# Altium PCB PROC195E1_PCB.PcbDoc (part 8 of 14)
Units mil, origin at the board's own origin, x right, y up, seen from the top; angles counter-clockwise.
Board outline 3110.24 x 2500 mil, 10 copper layers (Top Layer, L02_GND1, L03_SIG1, L04_GND2, L05_PWR1, L06_PWR2, L07_GND3, L08_SIG2, L09_GND4, Bottom Layer), stack 66.407 mil thick; 571 components, 538 nets, 6726 pads, 1286 vias.
Unrouted connection lines stored in the file: 4.
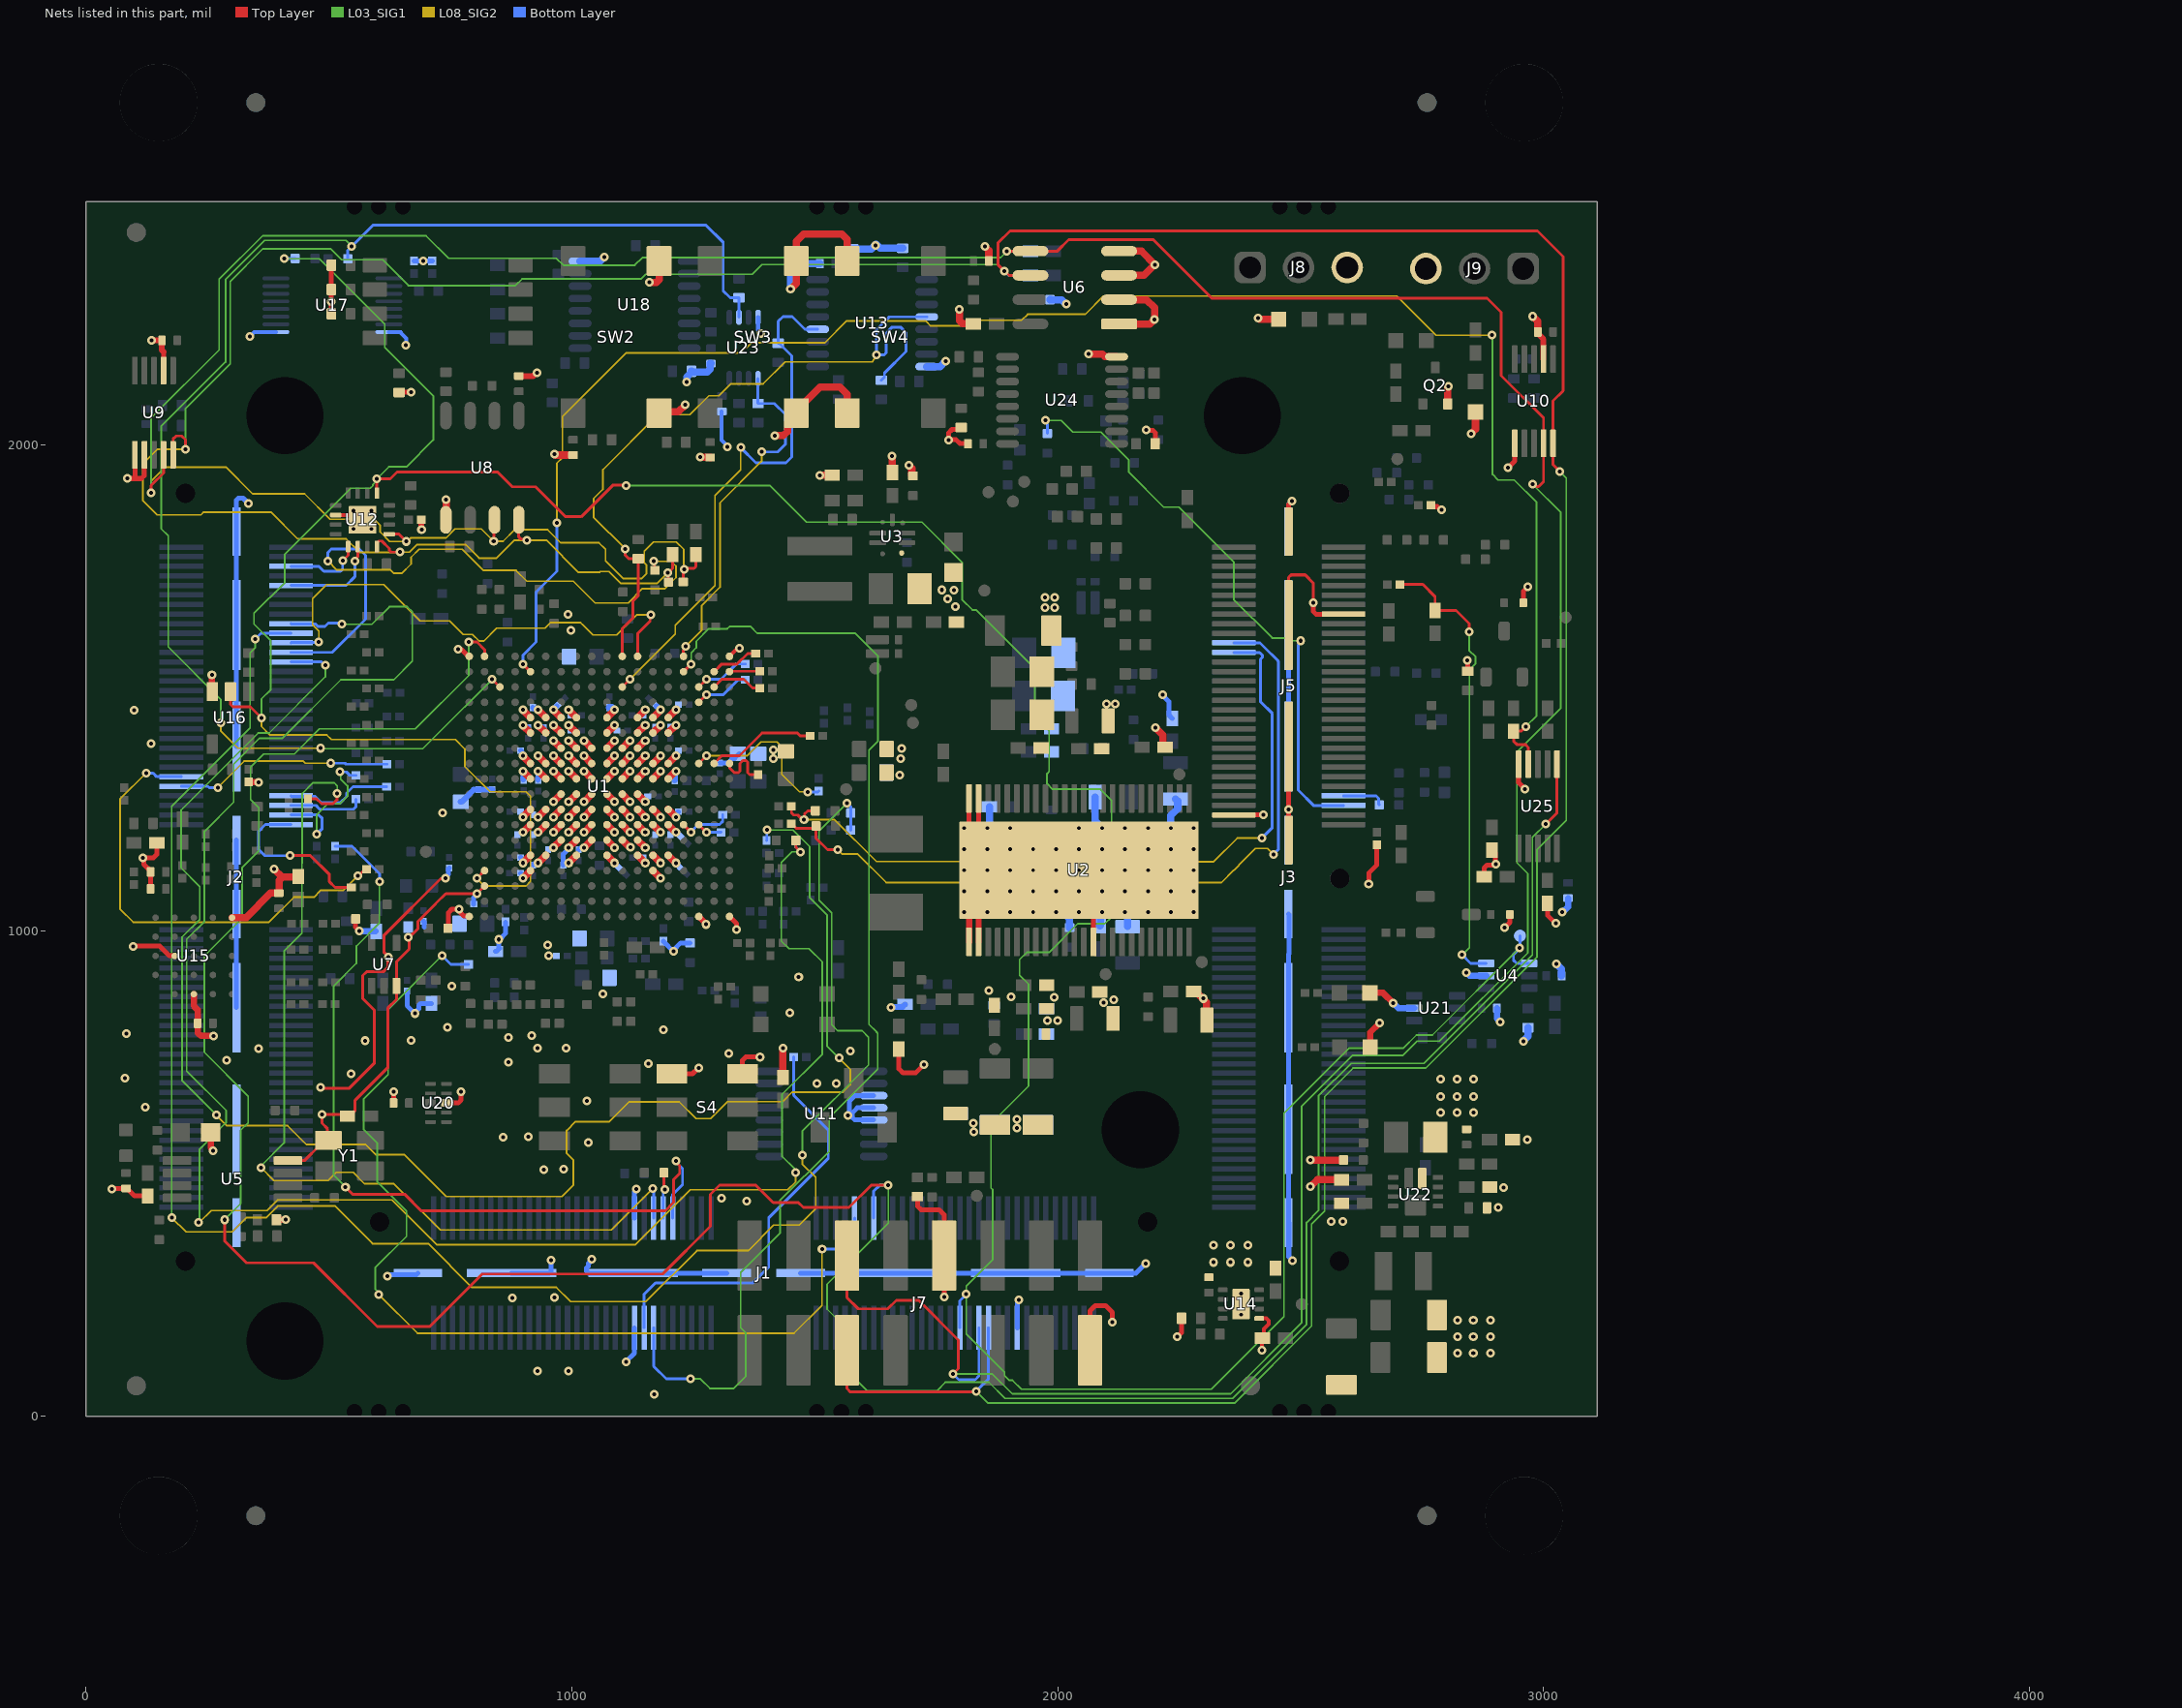
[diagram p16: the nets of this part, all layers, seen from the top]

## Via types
v1: diameter 18, hole 8, Top Layer to Bottom Layer, tented both sides, 1226 vias
v2: diameter 19.68, hole 7.87, Top Layer to Bottom Layer, tented top, 54 vias
v3: diameter 19.68, hole 7.87, Top Layer to Bottom Layer, 4 vias
v4: diameter 19.68, hole 7.87, Top Layer to Bottom Layer, tented both sides, 2 vias

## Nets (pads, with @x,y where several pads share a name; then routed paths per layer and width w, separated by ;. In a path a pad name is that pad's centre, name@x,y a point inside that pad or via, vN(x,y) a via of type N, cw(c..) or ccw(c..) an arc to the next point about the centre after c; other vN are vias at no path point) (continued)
GND: C1.2 C2.2 C3.2 C4.2 C5.2 C6.2 C7.2 C8.2 C9.2 C10.2 C11.2 C12.2 C13.2 C14.2 C15.2 C16.2 C17.2 C18.2 C19.2 C20.2 C21.2 C22.2 C23.2 C24.2 C25.2 C26.2 C27.2 C28.2 C29.2 C30.2 C31.2 C32.2 C33.2 C34.2 C35.2 C36.2 C37.2 C38.2 C39.2 C40.2 C41.2 C42.2 C43.2 C44.2 C45.2 C46.2 C47.2 C48.2 C49.2 C50.2 C51.2 C52.2 C53.2 C54.2 C55.2 C56.2 C57.2 C58.2 C59.1 C60.1 C62.2 C63.2 C64.2 C65.1 C66.1 C67.2 C68.2 C69.2 C70.2 C73.2 C74.2 C75.1 C76.2 C77.2 C78.2 C79.2 C80.2 C81.2 C82.1 C83.1 C84.2 C85.2 C86.2 C87.1 C88.1 C89.1 C90.1 C91.2 C92.2 C93.2 C94.2 C95.2 C96.1 C97.2 C98.2 C99.2 C100.1 C101.2 C102.1 C103.1 C104.2 C105.2 C107.2 C109.2 C111.2 C112.2 C113.2 C114.2 C115.2 C116.2 C117.2 C118.2 C119.2 C122.1 C129.2 C130.1 C131.2 C132.2 C137.2 C138.2 C139.2 C140.2 C141.2 C152.2 C153.1 C154.1 C155.2 C156.2 C157.2 C158.2 C159.2 C160.2 C161.2 C167.2 C168.2 C169.2 C174.2 D5.1 D6.1 D7.1 D8.1 D9.1 D10.1 J1.17 J1.77 J1.78 J1.121 J1.122 J1.123 J1.124 J1.125 J1.126 J1.127 J1.128 J2.121 J2.122 J2.123 J2.124 J2.125 J2.126 J2.127 J2.128 J3.121 J3.122 J3.123 J3.124 J3.125 J3.126 J3.127 J3.128 J5.16 J5.57 J5.P1 J5.P2 J5.P3 J5.P4 J7.2 J7.7 J8.3 J9.3 Q2.2 R2.1 R13.1 R17.1 R26.1 R28.2 R31.1 R32.1 R33.1 R35.1 R42.1 R51.1 R53.1 R69.2 R78.1 R148.2 R166.1 R188.1 R194.1 R200.1 R201.1 R209.1 R227.1 R228.1 R229.1 R230.1 R251.2 R258.2 R259.2 R269.2 R270.2 R271.1 R281.1 R302.2 R303.2 R309.2 SW2.1 SW2.3 SW3.1 SW3.3 SW4.1 SW4.3 U1.A1 U1.A18 U1.E5 U1.E6 U1.E7 U1.E8 U1.E10 U1.E12 U1.E13 U1.E14 U1.F5 U1.F6 U1.F7 U1.F8 U1.F10 U1.F12 U1.F13 U1.F14 U1.G7 U1.G8 U1.G9 U1.G10 U1.G11 U1.G12 U1.H5 U1.H6 U1.H7 U1.H8 U1.H9 U1.H10 U1.H11 U1.H12 U1.H13 U1.H14 U1.J5 U1.J6 U1.J7 U1.J8 U1.J9 U1.J10 U1.J11 U1.J12 U1.J13 U1.J14 U1.K7 U1.K8 U1.K9 U1.K10 U1.K11 U1.K12 U1.L5 U1.L6 U1.L7 U1.L8 U1.L9 U1.L10 U1.L11 U1.L12 U1.L13 U1.L14 U1.M5 U1.M6 U1.M7 U1.M8 U1.M9 U1.M10 U1.M11 U1.M12 U1.M13 U1.M14 U1.N7 U1.N8 U1.N9 U1.N10 U1.N11 U1.N12 U1.P5 U1.P6 U1.P8 U1.P10 U1.P12 U1.P13 U1.P14 U1.R5 U1.R13 U1.T2 U1.V1 U1.V16 U1.V18 U2.1 U2.2 U2.14 U2.47 U2.48 U2.49 U3.4 U4.2 U5.4 U6.1 U6.2 U6.3 U6.4 U7.3 U8.5 U9.1 U9.2 U9.7 U10.1 U10.7 U11.11 U11.12 U11.13 U12.6 U12.17@569.55,1845.49 U13.8 U14.5 U14.9 U15.B3 U15.C1 U15.E5 U16.3 U17.8 U17.9 U18.8 U20.3@742.01,645.23 U21.2 U22.5 U23.4 U24.8 U25.5 Y1.2 | length 14704.5
  Top Layer w5.6: U1.T2@820.66,1091.48 U1.T2@820.66,1091.97
  Top Layer w5.66: 782.6,1076.22 787.91,1076.22 787.96,1076.26 804.87,1076.26 v1(804.91,1076.22)
  Top Layer w5.8: 720.46,1055.73 740.94,1076.22 782.6,1076.22
  Top Layer w6: U5.4@416.14,526.56 449.87,526.56 481.25,557.95 491.46,568.15 Y1.2@499.33,568.15 497.6,569.88 497.6,591.91 486,603.51 v1(486,621.89) 534.81,621.89 C130.1@538.62,618.07 ; v1(482.81,676.91) 483.88,675.84 542.51,675.84 594.13,727.46 594.13,835.85 569.88,860.1 569.88,907.34 577.76,915.23 612.26,915.23 622.08,925.05 v1@622.08,947.14 ; C130.1@538.7,618.15 542.64,618.15 554.45,629.96 554.45,650.72 621.28,717.56 621.28,840.1 639.57,858.39 U7.3@639.57,886.14 639.57,935.97 665.71,962.11 665.71,983.81 v1(663.47,986.04) ; v1(622.52,945.86) 622.52,946.7 613.48,955.74 613.48,989.9 730.55,1106.97 738.82,1106.97 v1(739.87,1108.02) ; v1@666.22,986.5 683.92,1004.2 683.92,1019.19 720.46,1055.73 ; v1(804.91,1076.22) U1.T2@820.66,1091.97 ; J5.P2@2475.38,1628.72 2475.38,1726.89 2480.63,1732.14 2509.46,1732.14 2525.71,1715.88 v1@2525.71,1675.24
  Top Layer w8: U12.6@514.43,1855.34 543.9,1855.34 550.85,1862.28 v3(550.85,1864.2) ; U1.A18@1324.6,1564.41 1339.13,1578.94 1343.12,1578.94 v1(1345.49,1581.3) ; U14.5@2415.32,202.21 2415.82,201.71 2429.4,201.71 2434.39,196.73 2434.39,190.1 2424.82,180.53 2424.82,164.63 C83.1@2421.59,161.4 ; v1(2420.77,136.59) 2420.77,160.68 C83.1@2421.54,161.45
  Top Layer w10: v1(54.07,468.19) 54.71,468.83 82.16,468.83 C116.2@82.8,469.48 84.77,469.48 100.52,453.73 C115.2@127.8,453.73 ; v1(85.51,1931.17) 86.25,1930.43 101.22,1930.43 ; v1(97.8,967.23) 98.56,967.99 152.49,967.99 172.39,948.09 182.85,948.09 U15.B3@182.96,947.98 ; U9.1@101.14,1979.36 101.22,1979.28 101.22,1930.43 ; U9.2@120.82,1979.36 120.03,1978.57 120.03,1936.28 114.17,1930.43 101.22,1930.43 ; C140.2@133.27,1085.78 C137.2@133.27,1120.78 133.27,1122.75 119.26,1136.76 119.26,1148.24 v1(117.72,1149.77) 139.18,1149.77 146.37,1156.96 R200.1@146.37,1180.75 ; U9.7@160.19,2152.59 160.19,2191.35 ; R228.1@505.5,2269.54 v1(505.5,2294.54) R229.1@505.5,2319.54 R230.1@505.5,2369.54 ; R53.1@555.32,1024.24 555.32,1006.96 562.51,999.77 v1(562.51,999.17) ; C152.2@633.35,645.23 633.46,645.33 633.46,667.97 v1(633.56,668.07) ; R227.1@644.79,2107.67 645.33,2108.21 669.06,2108.21 v1(669.6,2108.76) ; U20.3@742.01,645.23 766.52,645.23 772.38,651.08 v1(772.38,668.85) ; R166.1@745.38,1004.78 746.7,1006.11 746.7,1037.26 753.36,1043.92 v1(767.91,1043.92) 769.44,1042.39 769.44,1038.25 777.77,1029.92 788.21,1029.92 U1.V1@789.16,1028.97 ; v1(766.13,1579.58) 767.66,1578.05 773.97,1578.05 787.61,1564.41 U1.A1@789.16,1564.41 ; U1.V18@1324.6,1028.97 1339.02,1014.55 1339.02,1002.8 v1(1339.43,1002.39) ; 1673.3,730.28 1673.3,715.7 1682.16,706.84 1707.6,706.84 v1(1724.57,723.81) ; 1673.3,731.28 C70.2@1673.3,756.03 ; R2.1@1711.47,452.57 1711.47,432.73 1718.71,425.5 1756.16,425.5 1766.47,415.19 J7.7@1766.47,331.06 1766.52,331.02 v1(1766.52,245.52) ; v1(1775.23,2010.01) v1@1775.23,2010.26 ; R259.2@1801.56,2035.56 1797.6,2031.59 1782.44,2031.59 1775.23,2024.39 v1@1775.23,2010.26 ; v2(1807.8,1210.92) 1810.36,1210.92 1817.64,1218.2 U2.48@1817.64,1271.95 ; C160.2@1815.39,2002.06 1814.58,2002.86 1798.42,2002.86 1791.03,2010.26 v1@1775.23,2010.26 ; U2.47@1837.32,1271.95 1837.32,1218.2 1844.6,1210.92 v2(1855.04,1210.92) ; J7.2@2066.47,136.18 2066.47,217.19 2077.3,228.03 2098.73,228.03 2112.67,214.09 v1(2112.67,194.48) ; U2.14@2073.54,976.67 2073.54,1030.42 2080.82,1037.7 v2(2091.26,1037.7) ; v1(2182.67,2030.73) 2184.2,2029.2 2196.47,2029.2 2200.66,2025.01 R258.2@2200.66,2002.06 ; v1(2246.45,164.33) 2246.74,164.33 2254.84,172.43 R42.1@2254.84,202.01 ; J5.57@2362.59,1237.97 v1@2422.96,1237.97 ; J5.P4@2475.38,1186.2 2475.19,1186.4 v1(2475.19,1249.34) 2475.19,1272 2475.38,1272.2 J5.P3@2475.38,1378.72 ; J5.P1@2475.38,1821.24 2475.38,1877.45 v1(2482.09,1884.24) v1(2482.09,1884.24) ; v1(2525.79,1675.17) 2525.79,1657.22 2531.65,1651.36 J5.16@2588.18,1651.36 ; v1(2640.09,1095.94) 2640.28,1096.12 2640.28,1118.49 2656.82,1135.03 R31.1@2656.82,1176.2 ; R26.1@2767.94,1875.9 2771.21,1872.63 2781.02,1872.63 2787.79,1865.86 v1(2789.96,1865.86) ; v1(2843.1,1556.55) 2843.46,1556.19 2843.46,1532.33 R281.1@2844.06,1531.73 ; R270.2@2877.76,1110.57 2877.76,1129.22 2883.62,1135.07 2900.4,1135.07 v1(2901.93,1136.61) 2901.93,1138.77 2900.32,1140.38 2900.32,1158.85 R269.2@2893.81,1165.35 ; v1(2919.51,1005.83) 2930.59,1016.91 D9.1@2930.59,1033.04 ; v1(2926.97,1952.88) 2940.74,1966.65 U10.1@2940.74,2002.97 ; U25.5@2948.83,1342.68 2948.83,1304.31 v1@2961.53,1291.61 ; D10.1@2958.26,1674.75 2958.26,1698.23 2967.01,1706.98 v1(2967.01,1707.78) ; R271.1@3007.89,1056.22 3007.89,1031.44 v1@3024.6,1014.73
  Top Layer w12: v1(135.48,2215.37) 135.78,2215.07 156.54,2215.07 C118.2@156.84,2214.77 156.84,2194.71 160.19,2191.35 ; C131.2@690.1,1845.49 690.56,1845.04 690.56,1825.48 v1(691.02,1825.02) ; C117.2@891.14,2141.56 920.57,2141.56 927.15,2148.13 v1(928.77,2148.13) ; U1.V16@1261.61,1028.97 1276.61,1013.97 v1(1276.61,1012.69) ; U2.2@1837.32,976.67 1837.32,1030.42 1844.6,1037.7 v2(1855.04,1037.7) ; C119.2@2988,2232.13 2989.88,2230.26 2989.88,2227.28 2999.79,2217.37 U10.7@2999.79,2176.2
  Top Layer w13: U15.C1@222.33,869.24 222.33,844.79 230.2,836.92 C139.2@230.2,809.24 230.2,789.42 235.18,784.44 236.56,784.44 237.71,783.29 v1(262.56,783.29) ; C129.2@257.19,584.5 257.19,553.62 262.2,548.6 v1(262.2,547.25) ; v1(259.54,1526.07) 259.97,1525.65 259.97,1492.36 U16.3@260.39,1491.94 ; C141.2@335.2,1305.85 335.55,1305.49 355.67,1305.49 v1(356.02,1305.14) ; R51.1@392.5,404.71 392.79,405.01 411.61,405.01 v1(411.91,405.3) ; v2(1807.8,1037.7) 1810.36,1037.7 1817.64,1030.42 U2.1@1817.64,976.67 ; D8.1@2642.6,871.87 2669.61,871.87 v1(2690.78,850.7) ; D5.1@2643.11,759.91 2643.11,790.23 v1(2662.48,809.6)
  Top Layer w15: U15.E5@301.07,1026.72 330.03,1026.72 380.52,1077.21 C138.2@397.38,1077.21 397.76,1077.58 397.76,1103.28 404.74,1110.25 ; v1(387.61,1126.45) 388.54,1125.52 388.54,1125.43 403.72,1110.25 404.74,1110.25 ; C75.1@437.28,1111.29 434.01,1111.29 432.97,1110.25 404.74,1110.25 ; U8.5@741.14,1845.49 741.39,1845.75 741.39,1886.78 v1(741.65,1887.03) ; v1(899.4,1107.71) U1.R5@915.15,1123.46 ; v1(899.4,1139.21) U1.P5@915.15,1154.96 ; v1(899.4,1202.2) U1.M5@915.15,1217.95 ; v1(899.4,1233.7) U1.L5@915.15,1249.45 ; v1(899.4,1328.19) U1.J5@915.15,1312.44 ; v1(899.4,1359.68) U1.H5@915.15,1343.93 ; v1(899.4,1422.67) U1.F5@915.15,1406.93 ; v1(899.4,1454.17) U1.E5@915.15,1438.42 ; v1(930.9,1139.21) U1.P6@946.64,1154.96 ; v1(930.9,1202.2) U1.M6@946.64,1217.95 ; v1(930.9,1233.7) U1.L6@946.64,1249.45 ; v1(930.9,1328.19) U1.J6@946.64,1312.44 ; v1(930.9,1359.68) U1.H6@946.64,1343.93 ; v1(930.9,1422.67) U1.F6@946.64,1406.93 ; v1(930.9,1454.17) U1.E6@946.64,1438.42 ; v1(962.39,1170.71) U1.N7@978.14,1186.45 ; v1(962.39,1202.2) U1.M7@978.14,1217.95 ; v1(962.39,1233.7) U1.L7@978.14,1249.45 ; v1(962.39,1265.19) U1.K7@978.14,1280.94 ; v1(962.39,1328.19) U1.J7@978.14,1312.44 ; v1(962.39,1359.68) U1.H7@978.14,1343.93 ; v1(962.39,1391.18) U1.G7@978.14,1375.43 ; v1(962.39,1422.67) U1.F7@978.14,1406.93 ; v1(962.39,1454.17) U1.E7@978.14,1438.42 ; v1(964.28,1980.5) 965.09,1980.5 966.82,1978.77 C155.2@1002.73,1978.77 ; v1(993.89,1139.21) U1.P8@1009.64,1154.96 ; v1(993.89,1170.71) U1.N8@1009.64,1186.45 ; v1(993.89,1202.2) U1.M8@1009.64,1217.95 ; v1(993.89,1233.7) U1.L8@1009.64,1249.45 ; v1(993.89,1265.19) U1.K8@1009.64,1280.94 ; v1(993.89,1328.19) U1.J8@1009.64,1312.44 ; v1(993.89,1359.68) U1.H8@1009.64,1343.93 ; v1(993.89,1391.18) U1.G8@1009.64,1375.43 ; v1(993.89,1422.67) U1.F8@1009.64,1406.93 ; v1(993.89,1454.17) U1.E8@1009.64,1438.42 ; v1(1025.39,1170.71) U1.N9@1041.13,1186.45 ; v1(1025.39,1202.2) U1.M9@1041.13,1217.95 ; v1(1025.39,1233.7) U1.L9@1041.13,1249.45 ; v1(1025.39,1265.19) U1.K9@1041.13,1280.94 ; v1(1025.38,1328.19) U1.J9@1041.13,1312.44 ; v1(1025.39,1359.68) U1.H9@1041.13,1343.93 ; v1(1025.39,1391.18) U1.G9@1041.13,1375.43 ; U1.P10@1072.63,1154.96 v1(1088.38,1139.21) ; U1.N10@1072.63,1186.45 1072.63,1186.31 1088.09,1170.85 v1(1088.09,1170.71) ; U1.M10@1072.63,1217.95 U1.M10@1072.63,1217.95 1088.19,1202.3 v1(1088.19,1202.2) ; U1.L10@1072.63,1249.45 1072.63,1249.3 1088.09,1233.84 v1(1088.09,1233.7) ; U1.K10@1072.63,1280.94 1072.63,1280.8 1088.09,1265.34 v1(1088.09,1265.19) ; U1.J10@1072.63,1312.44 v1(1088.38,1328.19) ; U1.H10@1072.63,1343.93 v1(1088.38,1359.68) ; U1.G10@1072.63,1375.43 v1(1088.38,1391.18) ; U1.F10@1072.63,1406.93 v1(1088.38,1422.67) ; U1.E10@1072.63,1438.42 v1(1088.38,1454.17) ; U1.N11@1104.12,1186.45 1118.56,1172.02 1120.04,1172.02 v1(1120.61,1171.45) ; U1.J11@1104.12,1312.44 v1(1119.87,1328.19) ; U1.H11@1104.12,1343.93 v1(1119.87,1359.68) ; U1.G11@1104.12,1375.43 v1(1119.87,1391.18) ; U1.M11@1104.17,1217.95 v1@1119.92,1202.2 ; U1.L11@1104.17,1249.45 v1@1119.92,1233.7 ; U1.K11@1104.17,1280.94 v1@1119.92,1265.19 ; U1.P12@1135.62,1154.96 v1(1151.37,1139.21) ; U1.N12@1135.62,1186.45 v1(1151.37,1170.71) ; U1.M12@1135.62,1217.95 v1(1151.37,1202.2) ; U1.L12@1135.62,1249.45 v1(1151.37,1233.7) ; U1.K12@1135.62,1280.94 v1(1151.37,1265.19) ; U1.J12@1135.62,1312.44 v1(1151.37,1328.19) ; U1.H12@1135.62,1343.93 v1(1151.37,1359.68) ; U1.G12@1135.62,1375.43 v1(1151.37,1391.18) ; U1.F12@1135.62,1406.93 v1(1151.37,1422.67) ; U1.E12@1135.62,1438.42 v1(1151.37,1454.17) ; v1(1159.85,2334.06) 1159.96,2334.17 1174.33,2334.17 1179.9,2339.73 SW2.1@1179.9,2378.25 ; U1.R13@1167.12,1123.46 v1(1182.86,1107.71) ; U1.P13@1167.12,1154.96 v1(1182.86,1139.21) ; U1.M13@1167.12,1217.95 v1(1182.86,1202.2) ; U1.L13@1167.12,1249.45 v1(1182.86,1233.7) ; U1.J13@1167.12,1312.44 v1(1182.87,1328.19) ; U1.H13@1167.12,1343.93 v1(1182.87,1359.68) ; U1.F13@1167.12,1406.93 v1(1182.86,1422.67) ; U1.E13@1167.12,1438.42 v1(1182.87,1454.17) ; SW2.3@1179.9,2065.26 1182.15,2067.51 1219.2,2067.51 1233.62,2081.93 v1(1233.62,2082.21) ; U1.P14@1198.61,1154.96 v1(1214.36,1139.21) ; U1.M14@1198.61,1217.95 v1(1214.36,1202.2) ; U1.L14@1198.61,1249.45 v1(1214.36,1233.7) ; U1.J14@1198.61,1312.44 v1(1214.36,1328.19) ; U1.H14@1198.61,1343.93 v1(1214.36,1359.68) ; U1.F14@1198.61,1406.93 v1(1214.36,1422.67) ; U1.E14@1198.61,1438.42 v1(1214.36,1454.17) ; v1(1264.84,1974.57) 1265.27,1974.14 1284.53,1974.14 C158.2@1284.9,1973.77 ; v1(1417.79,2018.78) 1435.19,2018.78 1443.97,2027.56 1443.97,2047.17 SW3.3@1462.07,2065.26 1462.07,2070.18 1510.98,2119.1 1551.88,2119.1 1567.07,2103.92 SW4.1@1567.07,2065.26 ; C122.1@1434.54,697.67 1434.8,697.93 1434.8,757.71 v1(1435.07,757.97) ; v1(1450.3,2320.41) 1462.07,2332.18 SW3.1@1462.07,2378.25 1462.07,2418.39 1477.3,2433.62 1555.7,2433.62 1567.07,2422.26 SW4.3@1567.07,2378.25 ; v1(1510.54,1936.77) 1510.8,1937.03 1535.7,1937.03 R32.1@1535.96,1937.28 ; v1(1659.16,1976.9) 1659.16,1943.46 C132.2@1659.81,1942.8 ; v1(1694.28,1957.97) 1694.28,1957.15 1699.93,1951.5 1699.93,1937.74 1701.78,1935.89 R35.1@1702.27,1935.89 ; v1(1797.3,2278.86) 1797.87,2278.29 1797.87,2255.34 1804.25,2248.96 1826.41,2248.96 C77.2@1826.76,2248.61 ; v1(1850.39,2408.17) 1858.38,2400.17 C159.2@1858.38,2378.25 ; v1(2063.38,2186.6) 2092.24,2186.6 2097.51,2181.34 2121.15,2181.34 U24.8@2121.29,2181.19 ; U6.1@2126.38,2248.61 2126.46,2248.53 2189.94,2248.53 2198.8,2257.39 v1(2199.61,2257.39) 2199.61,2282.01 2183.06,2298.55 U6.2@2126.38,2298.61 U6.2@2126.38,2298.61 ; U6.3@2126.38,2348.61 2177.78,2348.61 v1@2197.58,2368.41 ; U6.4@2126.38,2398.61 2172.22,2398.61 v1(2200,2370.83) ; v1(2200.92,1417.81) 2216.34,1402.38 2216.34,1381.81 2220.66,1377.5 C112.2@2220.84,1377.5 ; C113.2@2279.68,874.92 2283.62,874.92 2306.52,852.03 2306.52,816.39 C109.2@2307.12,815.79 ; v1(2412.07,2260.33) 2412.89,2260.33 2415.03,2258.18 2454.76,2258.18 D7.1@2454.88,2258.07 ; v1(2519.79,472.76) 2534.08,487.06 R194.1@2584.37,487.06 ; v1(2519.79,527.84) R188.1@2588.42,527.84 ; Q2.2@2802.7,2084.02 2802.7,2118.22 2803.68,2119.21 v1(2803.68,2120.02) ; v1(2851.03,2022.56) 2851.03,2023.38 2859.8,2032.14 D6.1@2859.8,2067.16 ; v1(2977.58,2264.24) 2988,2253.82 C119.2@2988,2232.13
  Bottom Layer w8: v1(338.04,2223.27) 346.96,2232.19 U17.9@391.42,2232.19 ; U17.8@623.7,2232.19 647.2,2232.19 647.26,2232.12 647.26,2231.18 659.18,2219.26 659.18,2205.79 v1@659.3,2205.67 ; C161.2@1308.76,2068.27 1308.76,2010.02 1320.73,1998.05 v1(1320.73,1995.35) ; U23.4@1383.53,2262.41 1383.53,2237.09 1389.21,2231.42 v1(1389.21,2228.71)
  Bottom Layer w10: J2.125@310,1033.82 J2.124@310,1186.18 ; J2.123@310,1378.7 J2.122@310,1628.7 310,1885.79 314.1,1889.89 323.74,1889.89 v1(334.34,1879.28) ; J2.126@310.17,841.47 J2.125@310.17,1033.65 ; v1(620.78,288.79) 622.94,288.79 625.69,291.54 680.32,291.54 J1.128@683.78,295 ; C57.2@661.15,875.41 661.15,845.51 677.33,829.34 v1(677.5,829.34) 677.5,831.5 685.05,839.05 685.05,846.11 689.15,850.21 R13.1@711.15,850.21 ; C78.2@675.4,2378.43 v1(694.79,2378.43) C76.2@713.06,2378.43 ; C54.2@694.96,1019.35 696.2,1018.11 696.2,1006.79 ; v1(739.87,1108.02) 739.87,1108.95 746.6,1115.68 746.6,1127.39 C23.2@747.89,1128.69 ; C46.2@798.57,1054.53 798.57,1068.42 ; C153.1@843.3,956.98 844.81,956.98 851.62,963.79 849.98,963.79 v1(849.98,981.79) ; v1@853.17,983.35 863.63,993.81 R148.2@863.63,1017.36 ; J1.127@876.3,295 953.9,295 957.37,298.47 v1(957.37,321.9) ; C53.2@894.5,1118.22 895.29,1118.22 896.58,1116.93 896.58,1112.7 899.4,1109.88 v1(899.4,1107.71) ; C12.2@894.95,1150.21 895.74,1150.21 897.04,1148.91 897.04,1143.74 899.4,1141.38 v1(899.4,1139.21) ; C8.2@894.95,1370.68 895.74,1370.68 897.04,1369.38 897.04,1368.6 897.87,1367.76 897.87,1361.21 v1(899.4,1359.68) ; v1(899.4,1328.19) 900.24,1327.35 900.24,1310.49 C24.2@901.08,1309.65 ; v1(899.4,1422.67) 901.57,1422.67 904.48,1419.76 909.1,1419.76 910.4,1418.46 C4.2@910.4,1417.67 ; C52.2@919.9,1134.76 919.9,1135.55 921.2,1136.85 921.98,1136.85 922.82,1137.68 929.37,1137.68 v1(930.9,1139.21) ; C47.2@919.9,1459.17 919.9,1458.38 921.2,1457.08 925.82,1457.08 928.73,1454.17 v1(930.9,1454.17) ; v1(930.9,1328.19) 930.99,1328.09 930.99,1309.51 C34.2@931.08,1309.42 ; v1(930.9,1422.67) 933.06,1422.67 935.97,1419.76 940.6,1419.76 941.9,1418.46 C15.2@941.9,1417.67 ; v1(962.39,1454.17) 962.39,1454.5 969.85,1461.96 C13.2@969.85,1462.28 ; C51.2@982.89,1134.76 982.89,1157.54 993.89,1168.54 v1(993.89,1170.71) ; C33.2@1014.39,1166.26 1014.39,1167.04 1015.68,1168.34 1016.47,1168.34 1017.3,1169.18 1023.85,1169.18 v1(1025.39,1170.71) ; v1(1041.14,323.48) 1041.14,321.31 1034.32,314.48 1034.32,309.04 1030.64,305.37 1030.64,299.08 1034.74,294.97 J1.126@1126.3,295 ; v1(1111.65,112.74) 1129.23,130.32 J1.77@1129.23,182.59 ; J1.126@1126.3,295 J1.125@1318.82,295 ; J1.78@1129.23,408.19 1129.38,408.33 1129.38,462.19 1132.89,465.7 v1(1132.89,467.87) ; C154.1@1188.84,978.42 1188.84,977.64 1209.4,957.08 v1(1209.49,957.08) ; v1@1209.49,959.81 1224.31,974.64 R78.1@1243.71,974.64 ; C37.2@1212.11,1308.17 1213.24,1309.3 1213.24,1327.06 v1(1214.36,1328.19) ; v1(1214.36,1233.7) 1215.89,1235.23 1215.89,1241.23 1217.27,1242.61 1217.27,1243.4 1218.57,1244.7 C9.2@1219.36,1244.7 ; C55.2@1304.96,1345.14 1321.67,1345.14 1330.71,1354.18 1334.87,1354.18 C2.2@1344.83,1364.14 ; J1.124@1471.18,295 J1.123@1663.7,295 J1.122@1913.7,295 2161.25,295 v1(2181.02,314.77) ; v1(1568.51,619.15) 1570.04,617.62 1575.37,617.62 1582.81,610.18 U11.13@1621.45,610.18 ; v1@1577.11,619.15 1577.11,622.07 v1@1575.85,623.33 ; U11.12@1621.45,635.18 1587.71,635.18 v1@1575.85,623.33 ; U11.11@1621.45,660.18 1582.33,660.18 1571.67,649.53 1571.67,627.5 v1@1575.85,623.33 ; J1.17@1916.75,182.59 1917.25,183.09 1917.25,234.72 1919.97,237.44 v1(1919.97,239.6) ; v1(2216.38,1485.83) 2216.38,1483.67 2228.94,1471.1 2228.94,1443.6 C114.2@2235.75,1436.79 ; J3.124@2475,1033.82 2475.7,1033.12 2475.7,951.96 2475,951.26 J3.123@2475,841.3 J3.122@2475,591.3 J3.121@2475,398.78 2475.67,398.11 2475.67,328.99 2482.87,321.79 v1(2482.87,320.48) ; J3.125@2475,1186.18 2475.09,1186.27 v1@2475.09,1249.34 ; J3.127@2475,1628.7 2475,1519.84 2475.09,1519.74 2475.09,1492.41 2475.05,1492.37 2475.05,1378.75 J3.126@2475,1378.7 2475,1249.53 v1(2475.19,1249.34) ; J3.128@2475,1821.22 2475,1877.05 2482.09,1884.14 v1(2482.09,1884.24)
  Bottom Layer w12: C3.2@771.55,1264.89 773.32,1264.89 798.56,1290.13 C43.2@808.13,1290.13 C41.2@836.65,1290.13 ; C14.2@1174.75,1461.63 v1@1182.55,1453.84 ; v1(1657.24,841.79) 1658.39,842.94 1680.74,842.94 R17.1@1685.99,848.2
  Bottom Layer w13: v1(562.51,999.17) R201.1@596.72,999.17 ; v1(2690.78,850.7) 2701.22,840.27 U21.2@2733.62,840.27 ; v1(2840.92,913.86) 2847.81,906.96 U4.2@2881.98,906.96 ; C156.2@2903.7,840.27 2903.7,819.63 2910.72,812.61 v1(2910.72,812.22) ; v1(3038.06,1037.84) 3039.42,1037.84 3049,1047.42 3049.22,1047.42 3050.22,1048.42 C174.2@3050.22,1066.8
  Bottom Layer w15: U18.8@1017.3,2377.79 1058.6,2377.79 v1(1067.46,2386.65) ; C42.2@1077.38,1459.17 1082.56,1459.17 1087.56,1454.17 v1(1088.38,1454.17) ; v1(1236.3,2129.69) 1236.87,2130.26 1236.87,2139.87 1246.5,2149.5 R309.2@1246.5,2151.47 1248.09,2149.88 1279.03,2149.88 1284.6,2155.45 1284.6,2166.78 1284.97,2167.16 C56.2@1286.71,2167.16 ; v1(1450.3,2320.41) 1450.3,2348.24 1475,2372.94 C105.2@1510.62,2372.94 ; R303.2@1578.39,2403.17 1616.64,2403.17 1624.12,2410.66 v1(1624.85,2410.66) ; v1@1626.02,2412.56 1626.83,2412.56 1634.86,2404.53 R302.2@1681.01,2404.53 ; U13.8@1730.57,2160.89 1730.71,2161.03 1757.75,2161.03 1768.95,2172.23 v1(1769.76,2172.23) ; v2(1855.04,1210.92) 1855.04,1212.19 1859.54,1216.69 C82.1@1859.54,1254.92 ; R69.2@1984.36,2298.61 1986.11,2298.61 1986.21,2298.51 2008.06,2298.51 2016.98,2289.58 v1(2017.8,2289.58) ; C81.2@1987.21,1210.98 1987.21,1178.45 1996.77,1168.88 v2(1996.77,1167.62) ; v2(1996.77,1037.7) 2011.01,1037.7 2024.45,1024.25 R28.2@2024.45,1006.19 ; C107.2@2077.06,1274.79 2077.06,1226.39 2091.26,1212.19 v2(2091.26,1210.92) ; C99.2@2087.28,1009.63 2088.19,1010.54 2088.19,1033.36 2091.26,1036.43 v2(2091.26,1037.7) ; v2(2138.5,1037.7) 2138.5,1036.43 2143.85,1031.08 C101.2@2143.85,1008.32 ; v2(2232.99,1210.92) 2232.99,1237.13 2247.01,1251.14 2247.01,1266.62 C111.2@2242.77,1270.86 ; v1(2958.2,772.26) 2968,782.06 R251.2@2968,800.17 ; v1(3026.56,931.81) 3026.56,930.99 3036.69,920.87 3036.69,907.34 C157.2@3037.06,906.96
  other v1: 1170.22,45.78 929.83,93.08 992.99,93.08 2822.5,129.84 2855.32,129.84 2890.58,129.84 2822.5,163.95 2855.32,163.95 2890.58,163.95 2822.5,198.07 2855.32,198.07 2890.58,198.07 878,244 964.41,244.63 2320.79,317.16 2356.05,317.16 2391.32,317.16 2320.79,352.42 2356.05,352.42 2391.32,352.42 2562.56,400.93 2586.68,400.93 2906.6,429.88 1359.7,442.88 1308.59,448.89 2917.72,470.89 942.97,508.18 983.71,508.98 1034.26,563.34 2966.54,569.69 859.35,575.15 910.62,576.11 1827.23,585.76 1915.77,593.42 1826.54,603.75 1915.69,611.33 2788,625.85 2822.12,625.85 2856.23,625.85 122.47,636.47 1030.9,649.78 2788,658.66 2822.12,658.66 2856.23,658.66 1544.32,684.94 1504.32,685.65 2788,693.93 2822.12,693.93 2856.23,693.93 80.38,696.58 546.29,705.07 1157.88,726.59 869.42,728.98 289.91,732.7 1323.34,747.51 1573.55,752.36 355.66,757.3 929.72,757.9 988.71,757.9 574.64,773.5 669.48,774.1 870.3,780.38 917.23,784.08 83.37,787.79 1188.61,795.78 744.54,801.24 1979.32,814.48 1999.7,814.9 1448.92,830.44 2094.43,851.9 2115.64,857.77 2299.46,860.24 1993.2,862.8 1904.09,863.72 1063.93,869.3 1858.05,876.68 752.82,885.32 1467.21,904.73 952.21,948.17 950.95,970.54 3025.38,1014.73 1119.96,1202.2 1119.96,1233.7 2423.59,1238.6 734.5,1242.02 1119.96,1265.19 2961.73,1291.61 1675.46,1320.37 1415.2,1353.64 1676.55,1353.97 1415.22,1371.64 1678.72,1374.92 134.1,1385.25 99.44,1453.62 2118.85,1466.47 2100.78,1466.95 998,1618 992.31,1650.67 1974.21,1664.61 1993.73,1664.61 1789.64,1667.32 1774.09,1682.88 1974.21,1685.97 1993.73,1685.97 1761.32,1701.24 1786.62,1700.96 658.79,2205.17
  other v2: 1902.28,1037.7 1949.53,1037.7 2044.02,1037.7 2185.75,1037.7 2232.99,1037.7 2280.24,1037.7 1807.8,1081 1855.04,1081 1902.28,1081 1949.53,1081 1996.77,1081 2044.02,1081 2091.26,1081 2138.5,1081 2185.75,1081 2232.99,1081 2280.24,1081 1807.8,1124.31 1855.04,1124.31 1902.28,1124.31 1949.53,1124.31 1996.77,1124.31 2044.02,1124.31 2091.26,1124.31 2138.5,1124.31 2185.75,1124.31 2232.99,1124.31 2280.24,1124.31 1807.8,1167.62 1855.04,1167.62 1902.28,1167.62 1949.53,1167.62 2044.02,1167.62 2091.26,1167.62 2138.5,1167.62 2185.75,1167.62 2232.99,1167.62 2280.24,1167.62 1902.28,1210.92 2044.02,1210.92 2138.5,1210.92 2185.75,1210.92 2280.24,1210.92
  other v3: 550.85,1826.79 588.25,1826.79 588.25,1864.2
  other v4: 2377.36,209.53 2377.36,252.83
INT_VREF1: S4.1 | length 59.8
  Top Layer w10: S4.1@1207.17,705.4 1248.7,705.4 1260.95,717.65 v1(1261.9,717.65)
INT_VREF2: S4.4 | length 67.2
  Top Layer w10: S4.4@1351.5,705.22 1351.5,733.28 1358.42,740.19 1386.98,740.19 v1(1387.52,739.65)
IOEXP_OUT_P6: J2.5 U12.9 | length 163.6
  Top Layer w5.8: v1(528.61,1761.12) 540.02,1772.53 U12.9@540.02,1790.38
  Bottom Layer w5.8: J2.5@422.41,1749.86 479.51,1749.86 489.87,1739.51 524.39,1739.51 528.61,1743.73 v1(528.61,1761.12)
IOEXP_OUT_P7: J2.9 U12.10 | length 203.2
  Top Layer w5.8: v1(553.65,1760.82) 553.65,1763.81 559.71,1769.87 U12.10@559.71,1790.38
  Bottom Layer w5.8: J2.9@422.41,1710.49 535.83,1710.49 553.65,1728.32 v1(553.65,1760.82)
JTAG_RESETn: R40.1 R64.1 U4.3 | length 948.4
  Top Layer w5.8: R64.1@2704.16,1712.47 2751.51,1712.47 2776.65,1687.33 R40.1@2776.65,1659 2819.87,1659 2846.75,1632.13 v1(2846.75,1615.26)
  L03_SIG1 w3.6: v1(2832.24,950.13) 2847.32,965.21 2847.32,1537.01 2859.9,1549.59 2859.9,1563.51 2846.75,1576.66 v1(2846.75,1615.26)
  Bottom Layer w5.8: v1(2832.24,950.13) 2849.81,932.55 U4.3@2881.98,932.55
MCAN1_RX/I2C1_SCL: R267.1 U1.B5 U25.4 | length 3614.6
  Top Layer w5.8: v1(899.4,1548.66) U1.B5@915.15,1532.91 ; v1(2963.32,1419.94) 2963.32,1419.84 2953.99,1410.51 2938.3,1410.51 R267.1@2938.15,1410.36 2938.15,1390.11 2945.06,1383.19 2962.01,1383.19 2968.52,1376.69 U25.4@2968.52,1342.68
  L03_SIG1 w3.6: v1(2894.14,2225.43) 2894.91,2224.65 2894.91,1939.08 2906.57,1927.42 2939.58,1927.42 2985.56,1881.44 2985.56,1442.18 v1@2963.38,1420
  L08_SIG2 w3.6: v1(969.29,1839.41) 969.29,1961.75 981.08,1973.54 981.08,2058.26 1112.08,2189.27 1348.91,2189.27 1369.29,2209.64 1520.54,2209.64 1565.84,2254.94 1728.63,2254.94 1738.69,2244.88 1816.62,2244.88 1828.02,2256.28 1925.96,2256.28 1938.28,2268.6 2056.64,2268.6 2093.96,2305.93 2698.18,2305.93 2778.68,2225.43 v1(2894.14,2225.43)
  Bottom Layer w5.8: v1(899.4,1548.66) 899.4,1566.39 926.94,1593.93 926.94,1696.98 969.67,1739.71 969.67,1839.03 v1(969.29,1839.41)
MCU_GPIO1: J1.52 R140.1 | length 2101.3
  L03_SIG1 w3.6: v1(603.09,250.72) 603.09,254.62 595.59,262.12 595.59,306.07 660,370.48 660,423.11 599.64,483.47 599.64,563.35 571.63,591.36 571.63,652.91 622.3,703.58 622.3,837.64 v1(733.05,948.39)
  L08_SIG2 w3.6: v1(603.09,250.72) 682.69,171.13 1457.69,171.13 1515.09,228.53 v1(1515.09,344.61)
  Bottom Layer w5.8: v1(733.05,948.39) 750.99,930.44 R140.1@787.59,930.44 ; v1(1515.09,344.61) 1570.22,344.61 1582.11,356.5 J1.52@1582.11,408.19
MCU_GPIO41: J2.19 R233.1 R236.1 | length 3918
  L03_SIG1 w3.6: v1(176.99,409.13) 176.99,1255.99 338.09,1417.09 338.09,1571.67 348.44,1582.02 v1(348.44,1599.76) ; v1(1474.62,537.94) 1474.62,587.27 1610.55,723.2 1610.55,780.84 1597.39,794 1546.96,794 1534.91,806.04 1534.91,1036.44 1509,1062.36 1509,1204.74 v1(1566.7,1262.44)
  L08_SIG2 w3.6: v1(176.99,409.13) 206.29,379.83 301.68,379.83 331.31,409.45 372.29,409.45 396.32,433.49 512.2,433.49 589.95,355.74 704.85,355.74 794.99,265.6 968.55,265.6 997.77,236.38 1152.55,236.38 1257.58,341.41 1363.34,341.41 1415.72,393.79 1468.49,393.79 1502.13,427.44 1502.13,492.13 1474.62,519.64 v1(1474.62,537.94)
  Bottom Layer w5.8: v1(348.44,1599.76) 360.45,1611.77 422.12,1611.77 J2.19@422.41,1612.07 ; v1(1566.7,1262.44) 1574.29,1254.85 1574.29,1242.34 R236.1@1574.06,1242.11 R233.1@1574.06,1206.89
MCU_GPIO42: J2.17 R234.1 R235.1 | length 4078
  Top Layer w5.8: R235.1@1461.22,1185.59 1461.22,1171.41 v1(1470.61,1162.03)
  L03_SIG1 w3.6: v1(232.03,399.31) 233.91,401.19 233.91,549.72 288.96,604.77 288.96,629.69 207.73,710.92 207.73,982.26 244.21,1018.75 244.21,1204.31 304.23,1264.33 304.23,1342.5 357.72,1395.99 404.64,1395.99 525,1516.35 634.05,1516.35 672.07,1554.36 672.07,1656.18 661.63,1666.61 624.81,1666.61 588.84,1630.63 v1(527.37,1630.63) ; v1(1460.7,501.55) 1457.95,504.31 1457.95,510.09 1433.16,534.87 1433.16,663.34 1515.71,745.89 1515.71,935.45 1488.43,962.73 1447,962.73 1431.37,978.37 1431.37,1140.3 1453.09,1162.03 v1(1470.61,1162.03)
  L08_SIG2 w3.6: v1(232.03,399.31) 233.91,399.31 258.37,423.77 373.03,423.77 395.1,445.84 630.02,445.84 722.51,353.36 1130.36,353.36 1243.78,466.78 1444.59,466.78 1460.7,482.89 v1(1460.7,501.55)
  Bottom Layer w5.8: J2.17@422.41,1631.75 422.89,1631.27 472.71,1631.27 477.82,1626.17 492.31,1626.17 499.11,1632.97 525.03,1632.97 v1(527.37,1630.63) ; R234.1@1461.22,1185.59 1461.22,1171.41 v1(1470.61,1162.03)
MCU_GPIO63: J2.52 R135.1 | length 449.3
  L08_SIG2 w3.6: v1(271.9,1294.36) 271.9,1294.82 325.77,1348.7 447.5,1348.7 451.67,1344.53 v1(504.29,1344.53)
  Bottom Layer w5.8: J2.52@196.81,1297.11 251.3,1297.11 254.04,1294.36 v1(271.9,1294.36) ; v1(504.29,1344.53) 533.41,1344.53 535.45,1342.48 R135.1@619.57,1342.48
MCU_GPIO64: J2.50 R136.1 | length 940.8
  Top Layer w5.6: v1(559.51,1112.62) 561.02,1112.62 568.99,1120.6 572.19,1120.6 R136.1@577.66,1126.07
  L08_SIG2 w3.6: v1(124.15,1324) 70.58,1270.43 70.58,1044.32 97.6,1017.3 376.81,1017.3 428.37,1068.86 469.35,1068.86 483.13,1082.64 529.54,1082.64 v1(559.51,1112.62)
  Bottom Layer w5.8: v1(124.15,1324) 138.85,1324 146.06,1316.79 J2.50@196.81,1316.79
MCU_GPIO67: J2.59 R143.1 | length 342.1
  Top Layer w5.8: v1(420.79,1154.37) 462.49,1154.37 501.47,1115.39 501.47,1100.5 513.13,1088.84 R143.1@546.52,1088.84
  Bottom Layer w5.8: v1(420.79,1154.37) 420.54,1154.13 368.61,1154.13 355.46,1167.28 355.46,1203.98 369.84,1218.37 J2.59@422.41,1218.37
MCU_GPIO68: J2.57 R144.1 | length 314.8
  L03_SIG1 w3.6: v1(475.48,1198.93) 475.48,1238.59 498.8,1261.9 523.63,1261.9 538.84,1277.11 538.84,1297.89 524.69,1312.03 524.69,1324.64 v1(522.71,1326.63)
  Bottom Layer w5.8: J2.57@422.41,1238.05 479.48,1238.05 486.51,1231.03 486.51,1209.96 v1(475.48,1198.93) ; v1(522.71,1326.63) 536.41,1326.63 543.4,1319.64 R144.1@555.81,1319.64
MCU_GPIO69: J2.55 R146.1 | length 154.6
  Bottom Layer w5.8: J2.55@422.41,1257.74 473.61,1257.74 481.49,1249.85 550.98,1249.85 555.81,1254.68 R146.1@555.81,1270.64
MCU_GPIO70: J2.53 R147.1 | length 220.7
  Bottom Layer w5.8: J2.53@422.41,1277.42 423.91,1275.92 472.11,1275.92 485.08,1262.95 499.91,1262.95 523.71,1262.95 536.85,1276.1 536.85,1283.01 550.06,1296.22 R147.1@619.29,1296.22
MCU_GPIO73: J1.75 R282.1 | length 861.1
  Bottom Layer w5.8: J1.75@1148.92,182.59 1148.92,251.41 1172.37,274.86 1372.58,274.86 1405.52,307.8 1405.52,408.67 1528.1,531.25 1528.1,589.92 1456.9,661.12 R282.1@1456.9,739.87
MCU_GPIO74: J2.25 R262.1 | length 3428.3
  L03_SIG1 w3.6: v1(269.39,620.44) 198.13,691.7 198.13,986.24 234.61,1022.72 234.61,1090.74 196.19,1129.16 196.19,1248.04 354.94,1406.79 377.54,1406.79 493.06,1522.31 493.06,1546.1 v1(493.32,1546.36) ; v1@1401.77,1207.09 1455.46,1207.09 1489.89,1172.65 1489.89,1067.89 1525.31,1032.46 1525.31,762.65 v1(1550.14,737.82)
  L08_SIG2 w3.6: v1(269.39,620.44) 269.39,619.12 290.01,598.51 415.51,598.51 454.34,559.67 576.06,559.67 596.63,539.1 654.85,539.1 741.48,452.47 979.79,452.47 1003.47,476.15 1003.47,527.7 989.65,541.52 989.65,588.38 1008.1,606.83 1077.31,606.83 1078.55,608.07 1117.85,647.38 1221.63,647.38 1255.77,613.24 1285.68,613.24 1320.37,647.93 1434.13,647.93 1453.74,667.53 1558.28,667.53 1573.25,682.49 1573.25,712.03 1573.25,714.72 v1(1550.14,737.82)
  Bottom Layer w5.8: J2.25@422.41,1553.01 484.68,1553.01 491.33,1546.36 v1(493.32,1546.36) ; R262.1@1401.07,1185.65 1401.4,1185.99 1401.4,1206.72 v1(1401.73,1207.05)
MCU_GPIO82: J1.48 U1.A2 U25.1 | length 6414.9
  Top Layer w5.8: v1(285.54,404.83) 285.54,361.19 330.62,316.1 468.7,316.1 599.93,184.86 707.86,184.86 816.17,293.17 1187.04,293.17 1285.13,391.26 1285.13,457.1 1304.37,476.35 1378.65,476.35 1414.53,440.47 1466.23,440.47 1476.69,430 1570.53,430 1616.26,475.73 v1(1651.46,475.73) ; v1(787.75,1594.03) 804.84,1594.03 820.66,1578.21 U1.A2@820.66,1564.41 ; v1(3004.66,1219.49) 3027.57,1242.4 U25.1@3027.57,1342.68
  L03_SIG1 w3.6: v1(285.54,404.83) 318.76,438.05 318.76,588.75 334.34,604.34 334.34,659.2 244,749.54 244,948.21 321.95,1026.15 321.95,1130.16 356,1164.22 356,1252.76 339.22,1269.54 339.22,1336.76 366.05,1363.59 429.39,1363.59 481.1,1415.29 678.19,1415.29 788.14,1525.24 788.14,1593.64 v1(787.75,1594.03) ; v1(1651.46,475.73) 1651.46,397.95 1525.53,272.02 1525.53,220.95 1570.1,176.38 1570.1,91.24 1608.84,52.49 1750.86,52.49 1768.91,70.53 1858.43,70.53 1891.99,36.97 2359.86,36.97 2512.23,189.33 2512.23,399.11 2536.73,423.62 2536.73,659.5 2603.98,726.75 2753.75,726.75 2977.07,950.07 2977.07,1191.9 v1(3004.66,1219.49)
  Bottom Layer w5.8: J1.48@1621.48,408.19 1621.48,463.63 1633.58,475.73 v1(1651.46,475.73)
MCU_GPIO85: J3.99 R104.1 R110.1 | length 1605
  Top Layer w5.8: R110.1@1452.17,1219.84 1452.96,1219.84 1458.32,1214.47 1458.32,1214.26 1462.28,1210.3 1497.82,1210.3 R104.1@1502.81,1215.29 1502.81,1212.67 1502.81,1190.19 1526.56,1166.44 v1(1547.39,1166.44)
  L08_SIG2 w3.6: v1(1547.39,1166.44) 1547.7,1166.44 1556.21,1157.94 1588.2,1157.94 1647.08,1099.07 2145.39,1099.07 2145.81,1098.65 2336.74,1098.65 2362.47,1124.38 2363.15,1124.38 2372.99,1134.23 2372.99,1134.9 2407.03,1168.94 2431.62,1168.94 v1(2443.89,1156.67)
  Bottom Layer w5.8: J3.99@2362.59,1592.3 2416.23,1592.3 2440.56,1567.97 2440.98,1567.97 2453.29,1555.66 2453.29,1554.72 2454.25,1553.76 2454.25,1167.03 v1(2443.89,1156.67)
MCU_GPIO86: J3.97 R105.1 R108.1 | length 1538.4
  Top Layer w5.6: R108.1@1452.17,1255.96 1452.21,1255.92 1452.21,1242.57 1456.88,1237.91 1465.28,1237.91 1474.99,1228.2 v1(1478.18,1228.2) ; v1@1477.99,1228.39 1479.27,1229.67 1479.27,1240.52 1485.38,1246.63 R105.1@1501.45,1246.63
  L08_SIG2 w3.6: v1(1478.18,1228.2) 1540.94,1228.2 1627.1,1142.04 1859.42,1142.04 1859.51,1141.95 1894.98,1141.95 2321.04,1141.95 2369.54,1190.45 v1(2420.73,1190.45)
  Bottom Layer w5.8: J3.97@2362.73,1572.48 2415.77,1572.48 2420.98,1567.27 2420.98,1562.12 2417.49,1558.63 2417.49,1543.33 2417.49,1471.12 2441.65,1446.97 2441.65,1211.95 2420.73,1191.03 v1(2420.73,1190.45)
MCU_GPIO119: J3.66 R173.1 | length 1217.8
  L03_SIG1 w3.6: v1(1974.61,2050.12) 2007.05,2050.12 2031.16,2026.02 2088.63,2026.02 2146.42,1968.22 2146.42,1943.35 2218.06,1871.71 2249.59,1871.71 2362.38,1758.92 2362.38,1681.22 2441.4,1602.2 2475.98,1602.2 2481.57,1596.61 v1(2499.95,1596.61)
  Bottom Layer w5.8: v1(1974.61,2050.12) 1974.61,2046.82 1978.68,2042.75 R173.1@1978.68,2023.2 ; v1(2499.95,1596.61) 2499.95,1593.31 2494.87,1588.23 2494.87,1289.18 2526.4,1257.66 J3.66@2588.19,1257.66
MCU_GPIO120: J3.68 R172.1 | length 88.3
  Bottom Layer w5.8: J3.68@2588.19,1277.34 2655.26,1277.34 2660.7,1271.9 2660.7,1260 R172.1@2661.82,1258.87
MCU_GPIO121: J1.70 R312.2 | length 1735.8
  Top Layer w5.8: v1(534.51,472.24) 534.51,471.85 548.88,457.48 656.07,457.48 690.02,423.53 1192.58,423.53 1209.31,440.27 1209.31,487.1 1222.16,499.95 1222.16,515.87 1214.19,523.85 v1(1214.19,525.64)
  L03_SIG1 w3.6: v1(534.51,472.24) 510.35,496.4 510.35,886 556.95,932.59 556.95,968.2 604.48,1015.73 v1(604.48,1101.3)
  Bottom Layer w5.8: R312.2@513.3,1173.35 547.78,1173.35 604.61,1116.51 v1@604.61,1101.3 ; J1.70@1207.97,408.19 1207.97,457.27 1228.06,477.35 1228.06,510.15 1214.19,524.03 v1(1214.19,525.64)
MCU_GPIO124: J1.72 R214.1 | length 95.5
  Top Layer w5.8: R214.1@1189.82,501.69 1189.82,474.09 1190.16,473.75 1190.16,467.96 v1(1191.41,466.7)
  Bottom Layer w5.8: J1.72@1188.29,408.19 1188.29,460.28 1191.41,463.4 v1(1191.41,466.7)
MCU_GPIO126: J1.73 U1.B15 | length 2401.7
  Top Layer w5.8: U1.B15@1230.11,1532.91 v1(1245.86,1548.66)
  L03_SIG1 w3.6: v1(1244.34,77.25) 1264.99,77.25 1284.45,57.8 1333.62,57.8 1358,82.18 1358,172.62 1347.83,182.79 1347.83,296.4 1428.67,377.24 1428.67,444.31 1529.83,545.47 1529.83,615.32 1627.41,712.9 1629.75,715.24 1629.75,788.79 1627.41,791.14 1611.64,806.9 1611.64,1371.07 1629.96,1389.38 1629.96,1565.53 1583.64,1611.85 1390.29,1611.85 1382.12,1611.85 1368.18,1625.78 1324.7,1625.78 1320.07,1621.16 1282.06,1621.16 1256.56,1595.65 1256.56,1582.42 1245.86,1571.71 v1(1245.86,1548.66)
  Bottom Layer w5.8: J1.73@1168.6,182.59 1168.78,182.41 1168.78,103 1194.52,77.25 v1(1244.34,77.25)
MCU_GPIO136: J2.23 R217.1 | length 1331.8
  Top Layer w5.8: v1(1169.22,1760.22) 1170.26,1759.17 1170.26,1742.72 R217.1@1171.31,1741.67
  L08_SIG2 w3.6: v1(498.49,1760.82) 516.85,1742.47 627.06,1742.47 634.2,1735.32 650.31,1735.32 669.49,1754.5 669.49,1768.53 685.97,1785.01 774.99,1785.01 818.66,1741.34 885.53,1741.34 907.69,1719.18 1003.39,1719.18 1048.16,1674.4 1116.13,1674.4 1145.76,1704.03 1192.12,1704.03 1214.68,1726.59 1214.68,1750.37 1204.84,1760.22 v1(1169.22,1760.22)
  Bottom Layer w5.8: J2.23@422.41,1572.7 507.21,1572.7 575.62,1641.11 575.62,1772.68 562.98,1785.32 505.13,1785.32 498.49,1778.68 v1(498.49,1760.82)
MCU_GPIO137: J2.21 U1.A12 | length 1048.2
  Top Layer w5.8: U1.A12@1135.62,1564.41 1135.62,1611.49 1153.78,1629.65 1161.32,1637.19 1161.32,1648.02 v1(1163.09,1649.79)
  L08_SIG2 w3.6: v1(479.57,1594.49) 479.57,1616.48 466.83,1629.22 466.83,1683.14 495.96,1712.26 612.94,1712.26 687.7,1637.5 748.5,1637.5 776.28,1609.73 795.79,1609.73 809.38,1596.14 819.16,1596.14 845.49,1622.46 944.89,1622.46 952.08,1629.65 956.3,1633.87 1018.37,1633.87 1022.59,1629.65 1043.5,1608.73 1092.18,1608.73 1113.09,1629.65 1133.23,1649.79 v1(1163.09,1649.79)
  Bottom Layer w5.8: J2.21@422.41,1592.38 423.47,1593.44 478.51,1593.44 v1(479.57,1594.49)
MCU_GPIO138: J1.74 R138.2 | length 1955.2
  Top Layer w5.8: R138.2@457.42,1271.47 474.71,1271.47 485.14,1261.04 508.83,1261.04 517.46,1269.67 v1(517.46,1282.02)
  L03_SIG1 w3.6: v1(360.65,512.11) 360.65,515.31 408.24,562.9 408.24,957.98 445,994.74 445,1138.19 445.39,1138.59 445.39,1282.04 467.67,1304.32 511.11,1304.32 517.46,1297.97 v1(517.46,1282.02)
  L08_SIG2 w3.6: v1(360.65,512.11) 387.33,485.43 498.69,485.43 515.78,502.52 550.19,502.52 573.88,478.82 634.37,478.82 729.45,383.75 1081.34,383.75 v1(1166.51,468.92)
  Bottom Layer w5.8: v1(1166.51,468.92) 1168.6,466.83 J1.74@1168.6,408.19
MCU_I2C0_SCL: J1.23 J7.12 R38.1 R49.1 R202.1 U6.6 U8.8 U9.5 U10.5 U12.12 | length 8866.2
  Top Layer w5.8: U9.5@179.88,1979.36 179.88,2012.04 186,2018.16 197.31,2018.16 205.04,2010.43 v1(205.04,1990.86) ; U12.12@599.08,1790.38 599.08,1797.46 603.53,1801.91 609.1,1801.91 624.67,1786.35 624.67,1782.55 628.22,1778.99 v1(646.94,1779.02) ; U8.8@891.14,1845.49 891.14,1810.05 895.4,1805.79 905.35,1805.79 v1(907.69,1803.45) ; R38.1@1199.16,1717.21 1198.52,1717.85 1198.52,1735.73 v1(1197.88,1736.37) 1198.43,1736.37 1207.93,1745.87 R202.1@1207.93,1773.82 ; J7.12@1566.47,136.18 1566.47,57.35 1573.59,50.23 1830.58,50.23 v1(1832.12,51.77) ; v1(1889.88,2357.75) 1877.62,2370.01 1877.62,2416.04 1901.95,2440.37 2987.15,2440.37 3040.07,2387.45 3040.07,2110.99 3019.48,2090.4 U10.5@3019.48,2002.97 3019.48,1959.27 3033.57,1945.17 v1(3033.57,1945.03) ; v1@1890.48,2358.34 1900.22,2348.61 U6.6@1944.01,2348.61
  L03_SIG1 w3.6: v1(205.04,1990.86) 205.04,2074.05 297.29,2166.3 297.29,2336.17 364.62,2403.5 503.74,2403.5 526.5,2380.74 610.87,2380.74 663.87,2327.74 884.34,2327.74 897.79,2341.19 1142.54,2341.19 1152.21,2350.86 1371.83,2350.86 1391.79,2370.82 1876.81,2370.82 v1(1889.88,2357.75) ; v1(1832.12,51.77) 1856.52,27.37 2363.84,27.37 2522.61,186.14 2522.61,395.92 2549.23,422.54 2549.23,658.43 2607.95,717.15 2757.73,717.15 2986.67,946.09 2986.67,1166.73 3046.67,1226.73 3046.67,1931.54 3033.57,1944.63 v1(3033.57,1945.03)
  L08_SIG2 w3.6: v1(205.04,1990.86) 147.72,1990.86 117.34,1960.48 117.34,1885.42 146.9,1855.86 237.15,1855.86 242.71,1861.43 380.97,1861.43 436.05,1806.34 535.81,1806.34 563.41,1778.74 646.66,1778.74 v1(646.94,1779.02) ; v1@647.1,1779.02 666.41,1779.02 681.99,1794.61 781.4,1794.61 809.33,1766.68 845.41,1766.68 882.18,1803.45 v1(907.69,1803.45) 947.84,1803.45 1013.92,1737.37 1057.35,1737.37 1058.92,1738.93 1076.54,1738.93 1100.64,1714.83 1175.99,1714.83 v1@1197.53,1736.37
  Bottom Layer w5.8: v1(1832.12,51.77) 1857.7,77.35 J1.23@1857.7,182.59 ; v1(1889.88,2357.75) 1890.25,2357.75 1899.38,2348.61 R49.1@1944.01,2348.61
MCU_I2C0_SDA: J1.25 J7.11 R39.1 R50.1 R203.1 U6.5 U8.7 U9.4 U10.4 U12.13 | length 8870.9
  Top Layer w5.8: v1(134.31,1900.57) 134.31,1916.29 160.19,1942.17 U9.4@160.19,1979.36 ; U12.13@624.67,1815.97 644.44,1815.97 v1(659.51,1800.9) ; v1(839.46,1801.33) 840.3,1802.17 840.3,1844.66 U8.7@841.14,1845.49 ; R39.1@1229.58,1717.72 v1@1229.58,1742.01 ; v1(1231.48,1743.9) 1233.41,1745.83 1251.9,1745.83 1255.29,1749.23 R203.1@1255.29,1773.82 ; J7.11@1566.47,331.06 1566.47,244.53 1589.61,221.39 1650.38,221.39 1667.79,238.8 1714.22,238.8 1795.76,157.26 1795.76,98.42 v1(1784.67,87.33) ; v1(1895.52,2398.46) 1895.59,2398.53 1943.93,2398.53 U6.5@1944.01,2398.61 1999.46,2398.61 2023.02,2422.17 2196.85,2422.17 2317.32,2301.7 2883.71,2301.7 2912.7,2272.71 2912.7,2142.42 2999.79,2055.33 U10.4@2999.79,2002.97 2999.79,1924.16 2989.66,1914.03 2985.23,1914.03 2980.25,1919.01 v1(2976.94,1919.01)
  L03_SIG1 w3.6: v1(134.31,1900.57) 134.31,2054.68 274.61,2194.98 274.61,2340.64 364.18,2430.21 700.28,2430.21 746.52,2383.96 968.34,2383.96 982.77,2369.54 1129.66,2369.54 1145.27,2385.14 1882.2,2385.14 v1(1895.52,2398.46) ; v1(1784.67,87.33) 1865.87,87.33 1906.64,46.57 2355.89,46.57 2501.86,192.54 2501.86,638.2 2606.53,742.88 2709.73,742.88 2739.36,772.51 2785.7,772.51 2967.47,954.27 2967.47,1117.19 2944.93,1139.72 2944.93,1367.35 3035.29,1457.71 3035.29,1860.66 v1(2976.94,1919.01)
  L08_SIG2 w3.6: v1(134.31,1900.57) 134.31,1924.55 163.72,1953.96 288.35,1953.96 343.31,1899 450.4,1899 502.85,1846.55 593.44,1846.55 605.89,1834.1 605.89,1820.24 625.23,1800.9 661.5,1800.9 668.82,1808.22 741.36,1808.22 759.93,1826.79 814,1826.79 v1(839.46,1801.33) 858.83,1801.33 882.49,1824.99 950.5,1824.99 977.17,1798.33 1056.02,1798.33 1069.63,1784.71 1069.63,1761.06 1105.8,1724.9 1144.26,1724.9 1154.11,1734.74 1154.11,1752.46 1149.51,1757.06 1149.51,1780.81 1168.52,1799.82 1215.31,1799.82 1230.71,1784.42 1230.71,1744.68 v1(1231.48,1743.9)
  Bottom Layer w5.8: v1(1784.67,87.33) 1796.29,75.72 1830.23,75.72 1838.01,83.5 J1.25@1838.01,182.59 ; v1(1895.52,2398.46) 1943.86,2398.46 R50.1@1944.01,2398.61
MCU_INTn: R41.2 U1.A15 U23.5 | length 720.9
  Top Layer w5.8: U1.A15@1230.11,1564.41 1229.97,1564.54 1229.97,1577.27 1234.42,1581.72 v1(1234.42,1585.06)
  L08_SIG2 w3.6: v1(1234.42,1585.06) 1267.58,1618.22 1267.58,1629.65 1267.58,1669.21 1305.09,1706.72 1305.09,1880.1 1390.93,1965.94 v1(1390.93,1985.62)
  Bottom Layer w5.8: R41.2@1383.24,2085.24 U23.5@1383.24,2136.13 ; R41.2@1383.53,2084.95 1417.04,2084.95 1439.56,2062.43 1439.56,2001.03 1423.7,1985.18 1391.37,1985.18 v1(1390.93,1985.62)
MCU_PORz: J1.29 R231.1 TP18.1 U1.R2 U4.4 U12.1 U16.2 | length 7757.4
  Top Layer w5.8: U16.2@297.79,1491.94 297.79,1465.36 302.67,1460.48 338.54,1460.48 v1(361.41,1437.6) ; U12.1@599.08,1900.61 599.04,1900.65 v1(599,1930) v1(599,1930) 626.91,1930 640.87,1943.96 847.4,1943.96 877.93,1913.43 925.54,1913.43 987.15,1851.83 1019.66,1851.83 1084.46,1916.63 1111.14,1916.63 v1(1111.67,1916.11) ; v1(804.91,1107.71) U1.R2@820.66,1123.46
  L03_SIG1 w3.6: v1(361.41,1437.6) 361.67,1437.87 361.67,1477.01 380.87,1496.2 380.87,1596.35 346.27,1630.95 346.27,1653.18 409.67,1716.58 409.67,1775.12 545.19,1910.64 585.68,1910.64 590.96,1915.92 590.96,1918.07 599,1926.1 v1(599,1930) 623.68,1954.68 660.17,1954.68 715.22,2009.73 715.22,2100.64 615.36,2200.49 615.36,2248.06 480.49,2382.94 v1(408.86,2382.94) ; v1(1111.67,1916.11) 1407.74,1916.11 1483.16,1840.68 1720.86,1840.68 1803.44,1758.11 1803.44,1681.2 1824.52,1660.12 1832.23,1660.12 1952.9,1539.45 1952.9,1441.02 1982.56,1411.36 1982.56,1327.5 1978.05,1322.99 1978.05,1302.29 1989.34,1291 2088,1291 2110.87,1268.13 2110.87,1027.97 2097.1,1014.2 2041.2,1014.2 1982.08,955.08 1936.4,955.08 1921.74,940.42 1921.74,908.26 1940,890 1940,679.74 1862.82,602.56 1862.82,470.16 1866.58,466.4 1866.58,323.04 1811.92,268.38 v1(1811.92,251.49) 1811.92,169.56 1890.67,90.82 1890.67,84.17 1900.51,74.33 1907.16,74.33 1925.32,56.17 2316.37,56.17 2465.69,205.48 2465.69,624.28 2599.27,757.85 2711.13,757.85 2738.22,784.94 2771.12,784.94 v1(2950.05,963.88)
  L08_SIG2 w3.6: v1(361.41,1437.6) 361.41,1420.78 379.5,1402.69 496.14,1402.69 505.56,1393.27 720.46,1393.27 760.65,1393.27 780.12,1373.8 780.12,1337.81 832.16,1285.77 906.22,1285.77 915.1,1276.89 915.1,1101.21 905.81,1091.92 829.91,1091.92 829.69,1091.7 820.92,1091.7 v1(804.91,1107.71)
  Bottom Layer w5.8: v1(408.86,2382.94) 409.07,2383.15 430.99,2383.15 R231.1@431.21,2383.37 ; J1.29@1798.64,182.59 1798.64,238.19 v1(1811.92,251.49) ; v1(2950.05,963.88) 2950.05,963.08 2938.04,951.07 2938.04,938.77 2944.26,932.55 U4.4@2970.56,932.55 ; v1@2951.32,964.35 TP18.1@2951.32,989.35
MCU_PR0_PRU0_GPIO11: R119.2 U1.M16 | length 54.1
  Top Layer w5.8: U1.M16@1261.61,1217.95 v1(1277.35,1202.2)
  Bottom Layer w5.8: v1@1276.14,1202.89 1276.48,1202.55 1307.33,1202.55 R119.2@1307.68,1202.2
MCU_PR0_PRU0_GPIO12: R121.2 U1.M15 | length 110
  Top Layer w5.8: U1.M15@1230.11,1217.95 v1(1245.86,1202.2)
  Bottom Layer w5.8: v1@1245.53,1203.12 1260.57,1218.17 1295.15,1218.17 1295.35,1218.37 1304.05,1218.37 1310.8,1225.12 R121.2@1310.8,1238.42
MCU_PR0_PRU0_GPIO13: R122.2 U1.H17 | length 226.5
  Top Layer w5.66: 1308.89,1359.73 1345.14,1359.73 1390.29,1404.88
  Top Layer w5.8: U1.H17@1293.1,1343.93 1308.89,1359.73 ; 1390.29,1404.88 1392.52,1407.11 1463.92,1407.11 1470.17,1400.85 R122.2@1490.87,1400.85
MCU_PR0_PRU0_GPIO14: R124.2 U1.H16 | length 341.3
  Top Layer w5.8: U1.H16@1261.61,1343.93 v1(1277.35,1359.68)
  L08_SIG2 w3.6: v1(1277.35,1359.68) 1360.68,1359.68 1389.44,1388.44 1422.18,1388.44 1432.4,1378.21 1432.4,1321.96 1468.76,1285.61 v1(1485.34,1285.61)
  Bottom Layer w5.8: v1(1485.34,1285.61) 1506.81,1285.61 R124.2@1508.32,1287.12
MCU_PR0_PRU0_GPIO16: R126.2 U1.H18 | length 115.5
  Top Layer w5.8: U1.H18@1324.6,1343.93 1325.57,1342.96 1325.57,1333.81 1334.01,1325.37 1343.13,1325.37 1346,1328.24 1346,1343.91 1351.8,1349.71 1359.31,1349.71 1362.32,1346.7 1362.32,1325.11 1366.56,1320.87 R126.2@1383.2,1320.87
MCU_PR0_PRU1_GPIO11: R137.2 U1.B18 | length 62.7
  Top Layer w5.8: U1.B18@1324.6,1532.91 1325.6,1533.91 R137.2@1386.87,1533.91
MCU_PR0_PRU1_GPIO12: R139.2 U1.B17 | length 100.9
  Top Layer w5.66: 1308.81,1548.61 1340.23,1548.61
  Top Layer w5.8: U1.B17@1293.1,1532.91 1308.81,1548.61 ; 1340.23,1548.61 1361.85,1570.23 R139.2@1378.58,1570.23
MCU_PR0_PRU1_GPIO13: R141.2 U1.D16 | length 114.9
  Top Layer w5.8: U1.D16@1261.61,1469.92 v1(1277.35,1485.67)
  Bottom Layer w5.8: v1(1277.35,1485.67) 1311.76,1485.66 1342.48,1516.39 R141.2@1357.23,1516.39
MCU_PR0_PRU1_GPIO14: R142.2 U1.C17 | length 106.5
  Top Layer w5.66: 1308.85,1517.16 1354.39,1517.16
  Top Layer w5.8: U1.C17@1293.1,1501.41 1308.85,1517.16 ; 1354.39,1517.16 1372.27,1499.28 R142.2@1385.71,1499.28
MCU_PR0_PRU1_GPIO16: R145.2 U1.C16 | length 115.2
  Top Layer w5.8: U1.C16@1261.61,1501.41 v1@1277.19,1517
  Bottom Layer w5.8: v1(1277.19,1517.07) 1277.28,1517.16 1307.18,1517.16 1338.72,1548.7 R145.2@1357.23,1548.7
MCU_RESETn: R232.1 R253.2 U1.C3 U23.2 | length 2992.7
  Top Layer w5.8: v1(836.41,1517.16) U1.C3@852.16,1501.41
  L03_SIG1 w3.6: v1(277.7,1427.74) 277.7,1476.17 169.65,1584.22 169.65,1812.86 155.21,1827.31 155.21,2037.79 287.69,2170.28 287.69,2340.15 368.16,2420.61 535.16,2420.61 v1(547.44,2408.34) ; v1(483.41,1375.41) 484.53,1374.29 693.53,1374.29 720.46,1401.21 v1(836.41,1517.16)
  L08_SIG2 w3.6: v1(277.7,1427.74) 277.7,1410.94 313.26,1375.38 v1(483.41,1375.41)
  Bottom Layer w5.8: R232.1@539.31,2382.89 539.31,2400.21 v1(547.44,2408.34) 591.41,2452.31 1276,2452.31 1311.81,2416.5 1311.81,2316.67 1326.06,2302.41 R253.2@1344.16,2302.41 U23.2@1344.16,2262.41
MCU_SPI0_CLK: R225.1 R298.2 U1.A11 U13.4 | length 1517.8
  Top Layer w5.8: U1.A11@1104.12,1564.41 1104.12,1621.98 1111.79,1629.65 1126.3,1644.16 1126.3,1678.72 1136.94,1689.35 R225.1@1136.94,1765.51 1117.34,1765.51 1110.39,1772.46 1110.39,1785.46 v1(1110.18,1785.67)
  L08_SIG2 w3.6: v1(1110.18,1785.67) 1045.01,1850.84 1045.01,1889.08 1064.11,1908.18 1064.11,1948.58 1177.45,2061.92 1243.24,2061.92 1282.32,2101 1303.18,2101 1327.68,2125.5 1394.06,2125.5 1439.31,2170.76 1618.34,2170.76 1620.89,2173.3 1620.89,2174.75 1627.13,2180.99 v1(1627.13,2184.88)
  Bottom Layer w5.8: R298.2@1637.24,2132.72 1643.56,2139.05 1643.56,2147.6 1688.08,2192.12 1688.08,2230.49 1676.43,2242.15 1659.47,2242.15 1647.3,2229.98 1647.3,2189.33 1643.02,2185.05 1626.96,2185.05 1627.13,2185.22 1627.13,2236.94 1653.44,2263.25 U13.4@1730.57,2263.25
MCU_SPI0_CS0: R301.2 U1.C11 U13.12 | length 1106
  Top Layer w5.8: U1.C11@1104.12,1501.41 v1(1119.87,1517.16)
  L08_SIG2 w3.6: v1(1119.87,1517.16) 1213.13,1610.41 1213.13,1628.33 1214.44,1629.65 1294.78,1709.99 1294.78,1895.46 1347.84,1948.52 v1(1347.84,1994.75)
  Bottom Layer w5.8: v1(1347.84,1994.75) 1347.84,1994.1 1379.12,1962.82 1440.78,1962.82 1452.56,1974.6 1452.56,2183.26 1426.88,2208.94 R301.2@1424.91,2208.94 1424.91,2254.16 1434.75,2264 1453.37,2264 1457.59,2259.77 1457.76,2259.77 1468.64,2248.9 1468.64,2248.73 1479.51,2237.85 1505.97,2237.85 U13.12@1506.16,2237.66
